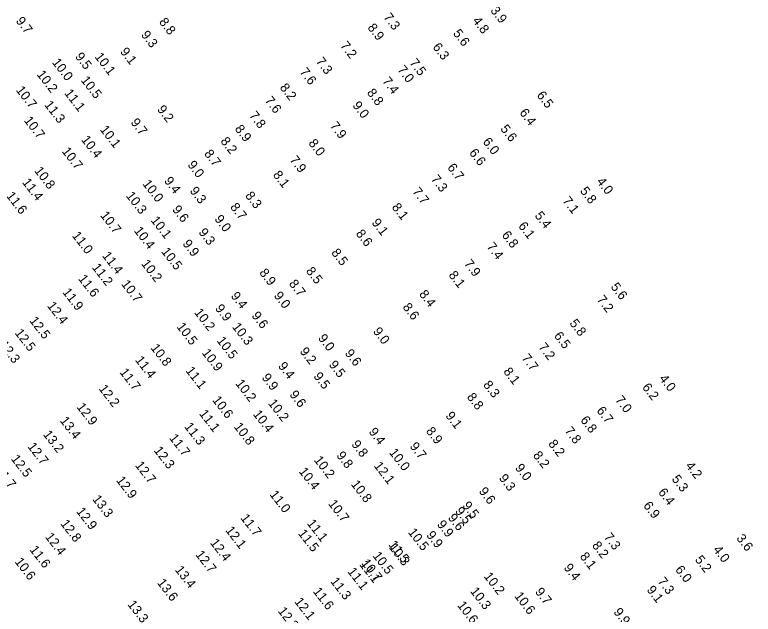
# Model space of a CAD drawing. Extents: x 815385 to 820851, y 582449 to 604245.
# Drawn here: x 819468.3 to 819863.9, y 593590.6 to 593911.8 of the extents above; entities that cross this region are included whole.
import ezdxf

# ---------------------------------------------------------------- set-up
doc = ezdxf.new("R2010")
doc.units = 0
for name, color, linetype in [('V-TOPO-SOUN-011609', 7, 'Continuous'), ('V-TOPO-SOUN-020509C', 7, 'Continuous'), ('V-TOPO-SOUN-112008', 7, 'Continuous'), ('V-TOPO-SOUN-EXCSS', 7, 'Continuous')]:
    doc.layers.add(name, color=color, linetype=linetype)

msp = doc.modelspace()

# ---------------------------------------------------------------- texts
at = {"layer": 'V-TOPO-SOUN-011609'}
for s, p in [('3.9', (819722.88, 593914.01)), ('9.7', (819468.64, 593908.37)), ('8.8', (819545.35, 593907.83)), ('7.3', (819665.6, 593910.38)), ('4.8', (819713.29, 593908.46)), ('8.9', (819657.05, 593904.81)), ('9.3', (819535.71, 593900.96)), ('5.6', (819702.85, 593901.72)), ('7.2', (819642.46, 593895.18)), ('9.1', (819524.51, 593891.9)), ('6.3', (819691.95, 593894.37)), ('10.1 ', (819510.88, 593889.19)), ('7.3', (819629.39, 593886.68)), ('7.5', (819679.54, 593885.93)), ('7.6', (819620.73, 593881.06)), ('7.0', (819673.1, 593882.23)), ('10.5 ', (819503.45, 593876.64)), ('7.4', (819664.99, 593876.11)), ('8.2', (819610.05, 593872.69)), ('11.1 ', (819494.62, 593869.7)), ('8.8', (819656.73, 593869.92)), ('6.5', (819747.71, 593868.56)), ('7.6', (819601.99, 593865.76)), ('11.3 ', (819483.89, 593863.46)), ('9.0', (819649, 593863.11)), ('7.8', (819593.67, 593857.72)), ('6.4', (819738.44, 593859.21)), ('10.7 ', (819473, 593855.06)), ('7.9', (819636.93, 593852.18)), ('8.9', (819585.94, 593850.53)), ('5.6', (819728.21, 593850.56)), ('8.2', (819578.27, 593843.96)), ('8.0', (819625.4, 593842.88)), ('6.0', (819718.77, 593843.65)), ('8.7', (819569.54, 593837.25)), ('6.6', (819711.49, 593837.73)), ('7.9', (819615.36, 593833.95)), ('9.0', (819560.63, 593831.3)), ('6.7', (819699.81, 593829.83)), ('8.1', (819606.38, 593825.91)), ('7.3', (819691.03, 593823.65)), ('10.0 ', (819536.52, 593821.12)), ('9.4', (819548.06, 593822.71)), ('4.0', (819779.78, 593822.34)), ('7.7', (819681.07, 593816.97)), ('5.8', (819770.88, 593817.32)), ('10.3 ', (819527.65, 593814.75)), ('8.3', (819591.51, 593814.78)), ('7.1', (819761.52, 593811.99)), ('8.7', (819583.45, 593808.68)), ('8.1', (819670.08, 593808.59)), ('5.4', (819746.6, 593804.08)), ('10.7 ', (819513.86, 593804.23)), ('9.0', (819575.06, 593802.25)), ('9.1', (819659.27, 593800.29)), ('6.1', (819737.84, 593798.52)), ('9.3', (819566.54, 593795.15)), ('8.6', (819650.79, 593794.44)), ('6.8', (819728.97, 593793.65)), ('9.9', (819557.97, 593789.04)), ('10.5 ', (819546.58, 593784.83)), ('7.4', (819720.94, 593787.44)), ('8.5', (819637.66, 593784.21)), ('10.2 ', (819535.83, 593778.32)), ('7.9', (819708.76, 593778.34)), ('8.5', (819624.06, 593774.36)), ('8.1', (819700.49, 593772.23)), ('8.7', (819614.95, 593767.6)), ('5.6', (819787.33, 593765.91)), ('9.0', (819606.86, 593761.2)), ('8.4', (819684.68, 593762.01)), ('7.2', (819779.93, 593759.12)), ('8.6', (819675.85, 593755.08)), ('9.6', (819594.94, 593750.49)), ('5.8', (819765.3, 593746.41)), ('10.3 ', (819584.54, 593744.51)), ('9.0', (819659.99, 593742.06)), ('6.5', (819756.94, 593739.67)), ('10.5 ', (819576.28, 593737.09)), ('7.2', (819748.62, 593733.65)), ('10.9 ', (819568.34, 593730.57)), ('9.6', (819644.88, 593730.35)), ('7.7', (819739.62, 593727.77)), ('9.5', (819636.31, 593724.24)), ('9.5', (819628.12, 593718.04)), ('8.1', (819729.84, 593720.53)), ('8.3', (819718.98, 593713.44)), ('4.0', (819813.3, 593716.76)), ('6.2', (819804.2, 593712.11)), ('9.6', (819615.23, 593708.22)), ('8.8', (819710.29, 593706.93)), ('7.0', (819789.77, 593705.35)), ('10.2 ', (819603.76, 593703.59)), ('10.4 ', (819595.68, 593697.75)), ('6.7', (819779.77, 593699.62)), ('9.1', (819698.82, 593696.85)), ('6.8', (819771.1, 593694.54)), ('8.9', (819688.36, 593688.61)), ('7.8', (819762.65, 593688.78)), ('8.2', (819753.88, 593681.86)), ('9.7', (819679.69, 593680.49)), ('10.0 ', (819668.6, 593677.17)), ('8.2', (819745.7, 593675.68)), ('12.1 ', (819660.47, 593670.05)), ('9.0', (819736.07, 593668.96)), ('4.2', (819827.41, 593670.04)), ('9.3', (819727.43, 593663.43)), ('5.3', (819820, 593662.98)), ('10.8 ', (819648.19, 593660.19)), ('9.6', (819716.68, 593656.39)), ('6.4', (819812.77, 593655.88)), ('10.7 ', (819636.02, 593649.71)), ('6.9', (819804.8, 593648.73)), ('9.5', (819703.93, 593645.79)), ('9.9', (819694.26, 593638.68)), ('10.5 ', (819678.76, 593634.45)), ('7.3', (819783.7, 593631.89)), ('3.6', (819854.66, 593631.24)), ('11.5 ', (819668.29, 593627.85)), ('8.2', (819777.32, 593627.38)), ('4.0', (819842.18, 593625.13)), ('10.5 ', (819659.8, 593621.86)), ('8.1', (819770.78, 593621.5)), ('5.2', (819832.46, 593619.8)), ('11.1 ', (819652.7, 593617.16)), ('9.4', (819762.18, 593615.46)), ('6.0', (819821.87, 593614.41)), ('7.3', (819812.49, 593608.12)), ('9.7', (819746.79, 593602.56)), ('9.1', (819806.61, 593603.63)), ('10.6 ', (819735.74, 593600.28)), ('9.9', (819788.87, 593591.73))]:
    msp.add_text(s, height=5, rotation=307.782, dxfattribs=at).set_placement(p)
at = {"layer": 'V-TOPO-SOUN-020509C'}
for s, p in [('10.8 ', (819478.55, 593828.13)), ('11.4 ', (819472.05, 593821.92)), ('11.6 ', (819463.49, 593814.7)), ('11.4 ', (819514.9, 593782.61)), ('11.2 ', (819509.46, 593776.32)), ('11.6 ', (819502.08, 593770.29)), ('11.9 ', (819493.63, 593763.09)), ('12.4 ', (819485.42, 593755.78)), ('12.5 ', (819475.93, 593747.81)), ('12.5 ', (819468.07, 593741.24)), ('12.3 ', (819459.73, 593734.83))]:
    msp.add_text(s, height=5, rotation=307.782, dxfattribs=at).set_placement(p)
at = {"layer": 'V-TOPO-SOUN-112008'}
for s, p in [('10.8 ', (819540.87, 593733.23)), ('11.4 ', (819532.56, 593726.72)), ('11.7 ', (819524.26, 593720.18)), ('12.2 ', (819513.06, 593711.38)), ('10.6 ', (819573.88, 593705.29)), ('12.9 ', (819501.21, 593701.58)), ('11.1 ', (819566.87, 593698)), ('13.4 ', (819492.25, 593694.24)), ('11.3 ', (819558.9, 593691.05)), ('13.2 ', (819483.24, 593686.88)), ('11.7 ', (819550.81, 593684.95)), ('12.7 ', (819474.92, 593680.38)), ('12.3 ', (819542.57, 593678.29)), ('12.5 ', (819466.05, 593673.79)), ('12.7 ', (819532.51, 593670.33)), ('11.7 ', (819457.57, 593667.72)), ('12.9 ', (819522.38, 593662.3)), ('11.0 ', (819604.61, 593654.7)), ('13.3 ', (819509.61, 593652.25)), ('12.9 ', (819501.01, 593645.64)), ('12.8 ', (819492.56, 593639.05)), ('11.7 ', (819589.01, 593642.09)), ('12.1 ', (819580.95, 593635.5)), ('12.4 ', (819484.31, 593632)), ('12.4 ', (819572.72, 593628.8)), ('11.6 ', (819476.01, 593625.14)), ('12.7 ', (819564.87, 593622.52)), ('10.6 ', (819468.05, 593618.7)), ('13.4 ', (819553.9, 593614.34)), ('11.1 ', (819646.33, 593613.41)), ('13.6 ', (819544.33, 593607.38)), ('11.3 ', (819637.14, 593608.16)), ('11.6 ', (819627.83, 593602.76)), ('13.3 ', (819528.47, 593595.79)), ('12.1 ', (819617.89, 593597.29)), ('12.3 ', (819609.05, 593592.24))]:
    msp.add_text(s, height=5, rotation=307.782, dxfattribs=at).set_placement(p)
at = {"layer": 'V-TOPO-SOUN-EXCSS'}
for s, p in [('9.5', (819500.37, 593889.29)), ('10.0 ', (819488.06, 593886.17)), ('10.2 ', (819479.85, 593879.74)), ('10.7 ', (819468.69, 593871.33)), ('9.2', (819544.34, 593861)), ('9.7', (819530.16, 593854.01)), ('10.1 ', (819513.72, 593850.2)), ('10.4 ', (819503.67, 593844.76)), ('10.7 ', (819493.29, 593838.56)), ('9.3', (819561.81, 593817.36)), ('9.6', (819552.42, 593807.36)), ('10.1 ', (819540.92, 593801.6)), ('11.0 ', (819498.75, 593793.39)), ('10.4 ', (819531.97, 593795.98)), ('8.9', (819599.07, 593773.48)), ('10.7 ', (819525.13, 593767.45)), ('9.4', (819583.81, 593761.07)), ('9.9', (819575.38, 593754.39)), ('10.2 ', (819564.22, 593752.19)), ('10.5 ', (819554.78, 593744.58)), ('9.0', (819630.55, 593738.43)), ('9.2', (819620.75, 593731.34)), ('9.4', (819609.14, 593723.47)), ('11.1 ', (819559.62, 593721.02)), ('9.9', (819600.37, 593717.32)), ('10.2 ', (819586.28, 593714.16)), ('10.8 ', (819585.46, 593691)), ('9.4', (819657.69, 593688.26)), ('9.8', (819648.42, 593681.57)), ('9.8', (819640.38, 593675.58)), ('10.2 ', (819628.33, 593673.15)), ('10.4 ', (819620.24, 593667.04)), ('9.5', (819707.86, 593648.76)), ('9.6', (819700.13, 593642.22)), ('11.1 ', (819624.6, 593639.22)), ('11.5 ', (819619.85, 593633.83)), ('9.9', (819688.54, 593632.93)), ('10.3 ', (819668.52, 593626.39)), ('10.7 ', (819653.77, 593617.93)), ('10.2 ', (819719.37, 593610.83)), ('10.3 ', (819712.07, 593602.88)), ('10.6 ', (819705.15, 593595.34))]:
    msp.add_text(s, height=5, rotation=307.782, dxfattribs=at).set_placement(p)

doc.saveas('drawing.dxf')
